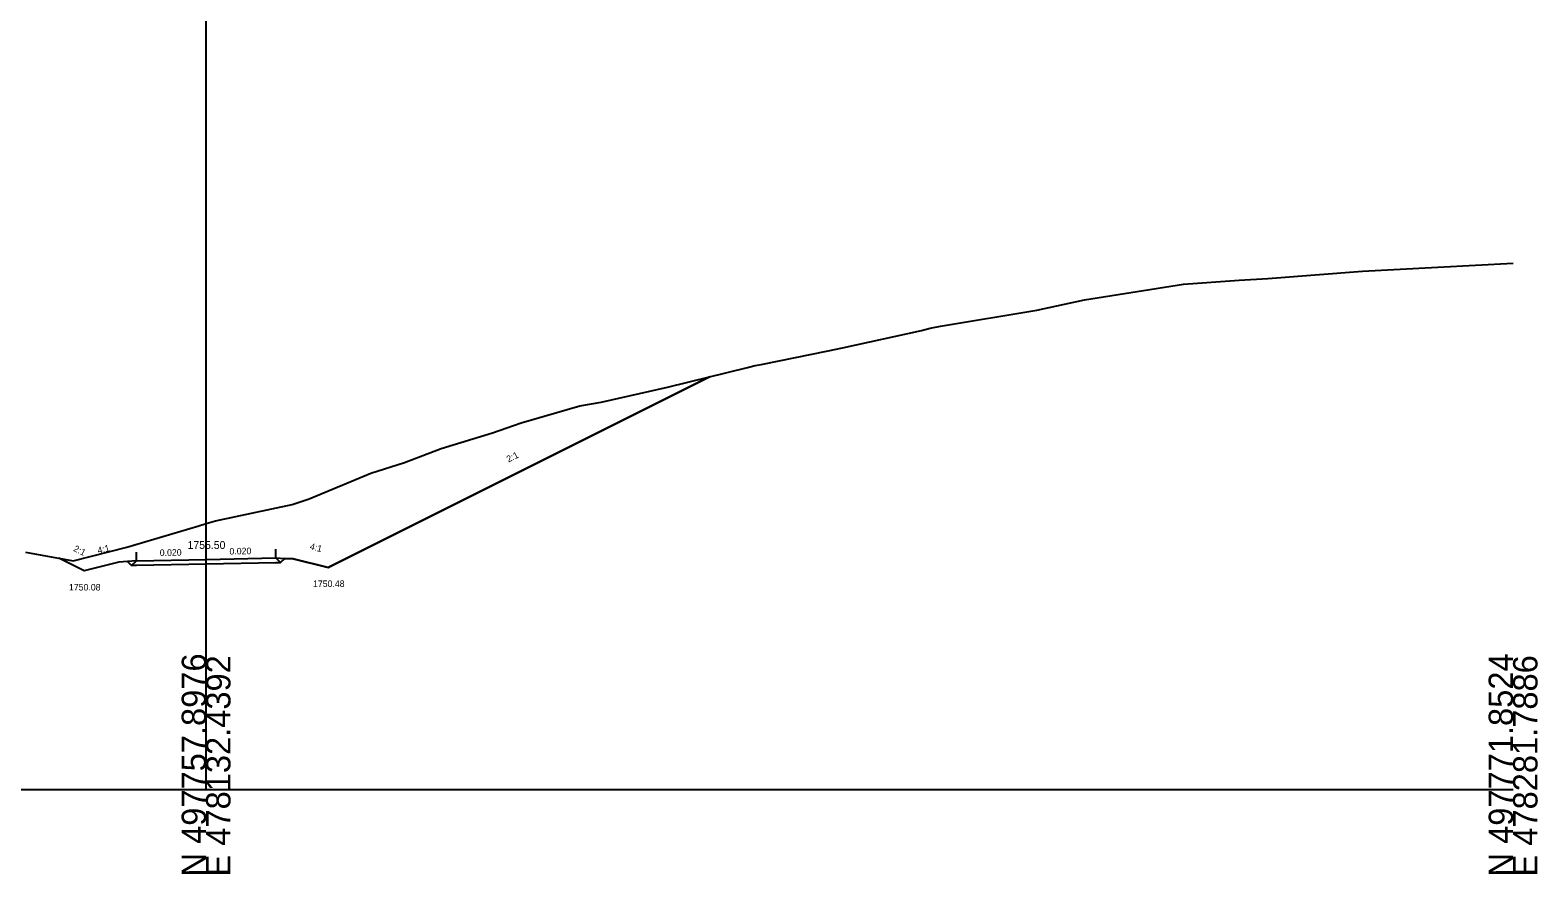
# Model space of a CAD drawing. Extents: x -26 to 303, y -10 to 3689.
# Drawn here: x 129.8 to 302.8, y 2490.3 to 2587.1 of the extents above; entities that cross this region are included whole.
import ezdxf

# ---------------------------------------------------------------- set-up
doc = ezdxf.new("R2010")
doc.units = 0
for name, color, linetype in [('Exist Cross Section Cell', 7, 'Continuous'), ('Exist XS Center Line Elevation Label', 7, 'Continuous'), ('Exist XS Ground Line', 7, 'Continuous'), ('Prop XS Ditch Slope Text', 7, 'Continuous'), ('Prop XS Ditch Standard Text', 7, 'Continuous'), ('Prop XS Dump Level', 7, 'Continuous'), ('Prop XS Earthwork Shape', 7, 'Continuous'), ('Prop XS EOT Tick Mark', 7, 'Continuous'), ('Prop XS Finish Grade', 7, 'Continuous'), ('Prop XS Finish Grade Earthwork', 7, 'Continuous'), ('Prop XS Finish Grade Pavement', 7, 'Continuous'), ('Prop XS Hydro Typical Ditch Data', 7, 'Continuous'), ('Prop XS Pvmt Edge Slope', 7, 'Continuous'), ('Prop XS SE Text', 7, 'Continuous'), ('Prop XS Shoulder Borrow Shape', 7, 'Continuous'), ('Prop XS Side Slope Text', 7, 'Continuous'), ('Prop XS Subgrade Earthwork', 7, 'Continuous')]:
    doc.layers.add(name, color=color, linetype=linetype)

msp = doc.modelspace()

# ---------------------------------------------------------------- linework, layer by layer
at = {"layer": 'Exist Cross Section Cell'}
for p, q in [((150, 2500), (150, 2681.14)), ((0, 2500), (150, 2500)), ((150, 2500), (300, 2500))]:
    msp.add_line(p, q, dxfattribs=at)
at = {"layer": 'Exist XS Ground Line'}
msp.add_lwpolyline([(129.29, 2527.21), (134.76, 2526.23), (140.92, 2527.81), (149.15, 2530.26), (150, 2530.5), (151.09, 2530.81), (159.89, 2532.69), (161.84, 2533.35), (168.9, 2536.29), (172.78, 2537.52), (176.98, 2539.13), (182.87, 2540.92), (186.16, 2542.06), (192.91, 2544.01), (195.35, 2544.44), (202.96, 2546.18), (212.14, 2548.44), (213.01, 2548.66), (213.72, 2548.78), (221.41, 2550.35), (223.05, 2550.68), (232.1, 2552.67), (233.1, 2552.93), (234.3, 2553.17), (245.35, 2555), (250.83, 2556.19), (262.16, 2557.97), (268.58, 2558.46), (271.85, 2558.64), (282.71, 2559.47), (300, 2560.38)], dxfattribs=at)
at = {"layer": 'Prop XS Dump Level'}
for p, q in [((142, 2526.24), (150, 2526.4)), ((150, 2526.4), (158, 2526.56))]:
    msp.add_line(p, q, dxfattribs=at)
at = {"layer": 'Prop XS Earthwork Shape'}
msp.add_lwpolyline([(140, 2526.08), (136, 2525.08), (133.09, 2526.53), (134.76, 2526.23), (140.92, 2527.81), (149.15, 2530.26), (150, 2530.5), (151.09, 2530.81), (159.89, 2532.69), (161.84, 2533.35), (168.9, 2536.29), (172.78, 2537.52), (176.98, 2539.13), (182.87, 2540.92), (186.16, 2542.06), (192.91, 2544.01), (195.35, 2544.44), (202.96, 2546.18), (207.76, 2547.36), (164, 2525.48), (160, 2526.48), (159.02, 2526.52), (158.53, 2526.03), (158, 2526.02), (150, 2525.86), (142, 2525.7), (141.45, 2525.69), (140.98, 2526.16)], close=True, dxfattribs=at)
msp.add_lwpolyline([(140, 2526.08), (136, 2525.08), (133.09, 2526.53), (134.76, 2526.23), (140.92, 2527.81), (149.15, 2530.26), (150, 2530.5), (151.09, 2530.81), (159.89, 2532.69), (161.84, 2533.35), (168.9, 2536.29), (172.78, 2537.52), (176.98, 2539.13), (182.87, 2540.92), (186.16, 2542.06), (192.91, 2544.01), (195.35, 2544.44), (202.96, 2546.18), (207.76, 2547.36), (164, 2525.48), (160, 2526.48), (159.02, 2526.52), (158.53, 2526.03), (158, 2526.02), (150, 2525.86), (142, 2525.7), (141.45, 2525.69), (140.98, 2526.16)], close=True, dxfattribs=at)
at = {"layer": 'Prop XS EOT Tick Mark'}
for p, q in [((142, 2526.24), (142, 2527.24)), ((158, 2526.56), (158, 2527.56))]:
    msp.add_line(p, q, dxfattribs=at)
at = {"layer": 'Prop XS Finish Grade'}
for p, q in [((158, 2526.56), (159.02, 2526.52)), ((142, 2526.24), (140.98, 2526.16))]:
    msp.add_line(p, q, dxfattribs=at)
at = {"layer": 'Prop XS Finish Grade Earthwork'}
for p, q in [((164, 2525.48), (207.76, 2547.36)), ((136, 2525.08), (133.09, 2526.53)), ((159.02, 2526.52), (160, 2526.48)), ((160, 2526.48), (164, 2525.48)), ((140, 2526.08), (136, 2525.08)), ((140.98, 2526.16), (140, 2526.08))]:
    msp.add_line(p, q, dxfattribs=at)
at = {"layer": 'Prop XS Finish Grade Pavement'}
for p, q in [((142, 2526.24), (150, 2526.4)), ((150, 2526.4), (158, 2526.56))]:
    msp.add_line(p, q, dxfattribs=at)
at = {"layer": 'Prop XS Hydro Typical Ditch Data'}
for p, q in [((136, 2525.08), (133.09, 2526.53)), ((140, 2526.08), (136, 2525.08))]:
    msp.add_line(p, q, dxfattribs=at)
at = {"layer": 'Prop XS Pvmt Edge Slope'}
for p, q in [((158, 2526.56), (158.53, 2526.03)), ((142, 2526.24), (141.45, 2525.69))]:
    msp.add_line(p, q, dxfattribs=at)
at = {"layer": 'Prop XS Shoulder Borrow Shape'}
for points in [[(158, 2526.56), (159.02, 2526.52), (158.53, 2526.03)], [(142, 2526.24), (140.98, 2526.16), (141.45, 2525.69)]]:
    msp.add_lwpolyline(points, close=True, dxfattribs=at)
at = {"layer": 'Prop XS Subgrade Earthwork'}
for p, q in [((158.53, 2526.03), (159.02, 2526.52)), ((141.45, 2525.69), (140.98, 2526.16)), ((142, 2525.7), (141.45, 2525.69)), ((150, 2525.86), (142, 2525.7)), ((158, 2526.02), (150, 2525.86)), ((158, 2526.02), (158.53, 2526.03))]:
    msp.add_line(p, q, dxfattribs=at)

# ---------------------------------------------------------------- texts
at = {"layer": 'Exist Cross Section Cell'}
for s, p in [('N 497757.8976', (150, 2490)), ('E 478132.4392', (152.8, 2490)), ('N 497771.8524', (300, 2490)), ('E 478281.7886', (302.8, 2490))]:
    msp.add_text(s, height=2.8, rotation=90, dxfattribs=at).set_placement(p)
at = {"layer": 'Exist XS Center Line Elevation Label'}
msp.add_text('1755.50', height=0.9, dxfattribs=at).set_placement((147.87, 2527.6))
at = {"layer": 'Prop XS Ditch Slope Text'}
for rotation, p in [(14.0362, (137.64, 2527.04)), (345.9638, (161.85, 2527.56))]:
    msp.add_text('4:1', height=0.75, rotation=rotation, dxfattribs=at).set_placement(p)
at = {"layer": 'Prop XS Ditch Standard Text'}
for s, p in [('1750.08', (134.26, 2522.83)), ('1750.48', (162.27, 2523.23))]:
    msp.add_text(s, height=0.75, dxfattribs=at).set_placement(p)
at = {"layer": 'Prop XS Dump Level'}
for p in [(160, 2526.44), (140, 2526.04)]:
    msp.add_text('Case1', height=0.04, dxfattribs=at).set_placement(p)
at = {"layer": 'Prop XS SE Text'}
for p in [(144.69, 2526.79), (152.69, 2526.95)]:
    msp.add_text('0.020', height=0.75, rotation=1.1458, dxfattribs=at).set_placement(p)
at = {"layer": 'Prop XS Side Slope Text'}
for rotation, p in [(26.5651, (184.7, 2537.51)), (333.4349, (134.71, 2527.4))]:
    msp.add_text('2:1', height=0.75, rotation=rotation, dxfattribs=at).set_placement(p)

doc.saveas('drawing.dxf')
